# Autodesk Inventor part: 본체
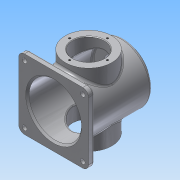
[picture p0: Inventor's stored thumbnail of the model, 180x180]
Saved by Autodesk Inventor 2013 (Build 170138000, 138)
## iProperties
Created: 2015-10
Part Number: 본체
Material: 알루미늄 6061
Document SubType Name: Modeling
Designer: Administrator
Mass: 988.451 g
Surface Area: 1040.91 cm^2
Volume: 364.742 cm^3
Density: 2.71 g/cm^3
Author: Administrator
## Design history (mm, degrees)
sketch "스케치1"
  geometry: C1 r 40 at (0, 0); 1 further point
  constraints: 1 centre point, 1 coincident
  dimensions: "d1" = 80 diameter of C1
extrude "돌출1" new body sketch "스케치1" stored distance "d2" = 124; taper "d3" = 0 deg
sketch "스케치2"
  geometry: C1 r 50 at (0, 0); 1 further point
  constraints: 1 centre point, 1 coincident
  dimensions: "d4" = 100 diameter of C1
extrude "돌출2" join sketch "스케치2" stored distance "d5" = 120; taper "d6" = 0 deg
sketch "스케치3"
  geometry: L1 (-60, -60)-(60, -60); L2 (60, -60)-(60, 60); L3 (60, 60)-(-60, 60); L4 (-60, 60)-(-60, -60); L5 (-60, -60)-(60, 60); L6 (60, -60)-(-60, 60); 1 further point
  constraints: 12 end point, 2 midpoint, 2 parallel, 1 horizontal, 1 perpendicular
  dimensions: "d7" = 120 distance of L3.end L2.end; "d8" = 120 distance of L2.end L1.end
extrude "돌출3" join sketch "스케치3" distance "d9" = 10; taper "d10" = 0 deg
sketch "스케치4"
  geometry: C1 r 40 at (0, 0); 1 further point
  constraints: 1 centre point, 1 coincident
  dimensions: "d11" = 80 diameter of C1
extrude "돌출4" join sketch "스케치4" distance "d12" = 5; taper "d13" = 0 deg
sketch "스케치5"
  geometry: L1 (40, 50)-(60, 50) reference; L2 (60, 50)-(60, 40) reference; L3 (60, 40)-(65, 40) reference; L4 (65, 40)-(65, -40) reference; L5 (65, -40)-(60, -40) reference; L6 (60, -40)-(60, -50) reference; L7 (60, -50)-(40, -50) reference; L8 (40, -50)-(40, -62) reference; L9 (40, -62)-(-40, -62) reference; L10 (-40, -62)-(-40, -50) reference; L11 (-40, -50)-(-50, -50) reference; L12 (-50, -50)-(-50, -60) reference; L13 (-50, -60)-(-60, -60) reference; L14 (-60, -60)-(-60, 60) reference; L15 (-60, 60)-(-50, 60) reference; L16 (-50, 60)-(-50, 50) reference; L17 (-50, 50)-(-40, 50) reference; L18 (-40, 50)-(-40, 62) reference; L19 (-40, 62)-(40, 62) reference; L20 (40, 62)-(40, 50) reference; L21 (52, 45)-(-60, 45); L22 (-60, 45)-(-60, 0); L23 (-60, 0)-(52, 0); L24 (52, 0)-(52, 45); 2 further points
  constraints: 8 end point, 2 midpoint, 2 parallel, 1 horizontal, 1 horizontal alignment, 1 perpendicular
  dimensions: "d14" = 5 distance between parallel lines of L1 L21; "d16" = 13 distance between parallel lines of L4 L24
revolve "회전1" sketch "스케치5" stored, may be unused: angle "d17" = 90 deg
hole "구멍1" diameter "d20" = 54; stored, may be unused: countersink angle "d24" = 90 deg, drill point angle "d26" = 0 deg; dims "d18" = 10, "d19" = 10, "d21" = 6, "d22" = 4, "d23" = 2, "d25" = 8
hole "구멍2" diameter "d29" = 54; stored, may be unused: countersink angle "d33" = 90 deg, drill point angle "d35" = 0 deg; dims "d27" = 10, "d28" = 10, "d30" = 6, "d31" = 4, "d32" = 2, "d34" = 8
sketch "스케치6"
  geometry: L1 (-50, -50)-(50, -50); L2 (50, -50)-(50, 50); L3 (50, 50)-(-50, 50); L4 (-50, 50)-(-50, -50); L5 (-50, -50)-(50, 50); L6 (50, -50)-(-50, 50); 5 further points
  constraints: 12 end point, 4 coincident, 2 midpoint, 2 parallel, 1 horizontal, 1 perpendicular
  dimensions: "d36" = 100 distance of L3.end L2.end; "d37" = 100 distance of L2.end L1.end
hole "구멍3" sketch "스케치6" at (-50, 50), (-50, -50), (50, -50), (50, 50) diameter "d38" = 8; stored, may be unused: countersink angle "d42" = 90 deg, drill point angle "d44" = 0 deg; dims "d39" = 6, "d40" = 4, "d41" = 2, "d43" = 8
sketch "스케치7" dims "d46" = 65
  geometry: L1 (0, 0)-(22.981, 22.981); L2 (0, 0)-(32.5, 0); 2 further points
  constraints: 4 end point, 2 coincident, 1 equal length, 1 horizontal, 3 other
  dimensions: "d47" = 45 deg angle of L2 L1
hole "구멍4" sketch "스케치7" at (22.981, 22.981) diameter "d48" = 3.459; stored, may be unused: countersink angle "d52" = 90 deg, drill point angle "d54" = 118 deg; dims "d49" = 8, "d50" = 4, "d51" = 2, "d53" = 10
sketch "스케치8"
  geometry: 2 further points
  constraints: 1 vertical alignment
  dimensions: "d58" = 32.5 distance of point (0, 0) point (0, 32.5)
hole "구멍5" sketch "스케치8" at (0, 32.5) diameter "d59" = 3.459; stored, may be unused: countersink angle "d63" = 90 deg, drill point angle "d65" = 118 deg; dims "d60" = 8, "d61" = 4, "d62" = 2, "d64" = 10
fillet "모깎기1" dims "d69" = 10
fillet "모깎기2" dims "d70" = 5
node "작업 평면1"
sketch "스케치9"
  geometry: L1 (60, 50)-(60, -50) reference; 2 further points
  constraints: 1 horizontal alignment, 1 other
  dimensions: "d71" = 70 distance from line of L1 point (-10, 0)
feature "엠보싱1" sketch "스케치9" dims "d3" = 0, "d11" = 80, "d72" = 0.5, "d73" = 0
fillet "모깎기3" dims "d74" = 5
chamfer "모따기1" distance "d75" = 1; stored, may be unused: second distance "d76" = 2, angle "d77" = 45 deg
fillet "모깎기4" dims "d78" = 3
fillet "모깎기5" dims "d79" = 3
fillet "모깎기6" dims "d80" = 5
fillet "모깎기7" dims "d81" = 3
fillet "모깎기8" dims "d82" = 3
chamfer "모따기2" distance "d83" = 3; stored, may be unused: second distance "d84" = 2, angle "d85" = 45 deg
node "솔리드1"
pattern_circular "원형 패턴1" dims angle "d56" = 360 deg
pattern_circular "원형 패턴2" dims angle "d67" = 360 deg
mirror "대칭1"
node "절단 모서리 투영1"
